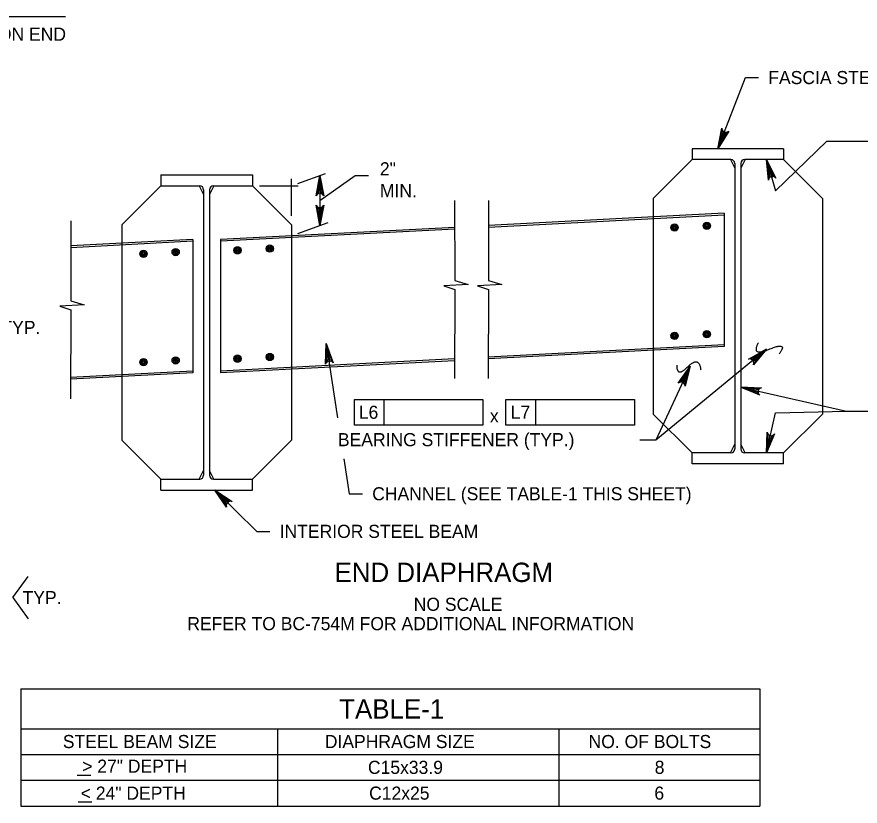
# Model space of a CAD drawing. Extents: x 638175 to 640495, y 294277 to 298435.
# Drawn here: x 639576.6 to 639769.6, y 296864 to 297044.7 of the extents above; entities that cross this region are included whole.
import ezdxf

# ---------------------------------------------------------------- set-up
doc = ezdxf.new("R2010")
doc.units = 0
for name, color, linetype in [('2', 7, 'Continuous'), ('3', 7, 'Continuous'), ('4', 7, 'Continuous'), ('5', 7, 'Continuous')]:
    doc.layers.add(name, color=color, linetype=linetype)

msp = doc.modelspace()

# ---------------------------------------------------------------- linework, layer by layer
at = {"layer": '2'}
for points in [[(639737.07, 297014.54), (639737.93, 297019.2), (639738.03, 297018.78), (639738.26, 297018.49), (639738.53, 297018.33), (639738.84, 297018.27), (639739.2, 297018.33), (639739.56, 297018.57), (639737.07, 297014.54), (639739.2, 297018.33), (639738.84, 297018.27), (639737.07, 297014.54), (639738.53, 297018.33), (639738.26, 297018.49), (639737.07, 297014.54), (639738.03, 297018.78)], [(639748.17, 297012.04), (639750.3, 297007.81), (639749.96, 297008.08), (639749.61, 297008.17), (639749.3, 297008.14), (639749.01, 297008), (639748.76, 297007.73), (639748.62, 297007.32), (639748.17, 297012.04), (639748.76, 297007.73), (639749.01, 297008), (639748.17, 297012.04), (639749.3, 297008.14), (639749.61, 297008.17), (639748.17, 297012.04), (639749.96, 297008.08)], [(639645.94, 297008.41), (639646.81, 297003.75), (639646.57, 297004.11), (639646.25, 297004.29), (639645.94, 297004.35), (639645.63, 297004.29), (639645.32, 297004.11), (639645.07, 297003.75), (639645.94, 297008.41), (639645.32, 297004.11), (639645.63, 297004.29), (639645.94, 297008.41), (639645.94, 297004.35), (639646.25, 297004.29), (639645.94, 297008.41), (639646.57, 297004.11)], [(639645.94, 296996.95), (639645.07, 297001.61), (639645.32, 297001.26), (639645.63, 297001.07), (639645.94, 297001.02), (639646.25, 297001.07), (639646.57, 297001.26), (639646.81, 297001.61), (639645.94, 296996.95), (639646.57, 297001.26), (639646.25, 297001.07), (639645.94, 296996.95), (639645.94, 297001.02), (639645.63, 297001.07), (639645.94, 296996.95), (639645.32, 297001.26)], [(639647.37, 296969.95), (639648.94, 296965.48), (639648.64, 296965.79), (639648.31, 296965.93), (639647.99, 296965.93), (639647.69, 296965.83), (639647.41, 296965.6), (639647.22, 296965.21), (639647.37, 296969.95), (639647.41, 296965.6), (639647.69, 296965.83), (639647.37, 296969.95), (639647.99, 296965.93), (639648.31, 296965.93), (639647.37, 296969.95), (639648.64, 296965.79)], [(639748.23, 296968.67), (639745.19, 296965.03), (639745.31, 296965.45), (639745.25, 296965.81), (639745.1, 296966.09), (639744.86, 296966.3), (639744.51, 296966.42), (639744.08, 296966.38), (639748.23, 296968.67), (639744.51, 296966.42), (639744.86, 296966.3), (639748.23, 296968.67), (639745.1, 296966.09), (639745.25, 296965.81), (639748.23, 296968.67), (639745.31, 296965.45)], [(639730.74, 296964.75), (639729.57, 296960.16), (639729.5, 296960.59), (639729.29, 296960.88), (639729.03, 296961.07), (639728.72, 296961.15), (639728.36, 296961.11), (639727.98, 296960.89), (639730.74, 296964.75), (639728.36, 296961.11), (639728.72, 296961.15), (639730.74, 296964.75), (639729.03, 296961.07), (639729.29, 296960.88), (639730.74, 296964.75), (639729.5, 296960.59)], [(639742.31, 296959.97), (639747.05, 296959.78), (639746.64, 296959.62), (639746.39, 296959.36), (639746.27, 296959.06), (639746.25, 296958.75), (639746.36, 296958.4), (639746.66, 296958.08), (639742.31, 296959.97), (639746.36, 296958.4), (639746.25, 296958.75), (639742.31, 296959.97), (639746.27, 296959.06), (639746.39, 296959.36), (639742.31, 296959.97), (639746.64, 296959.62)], [(639748.17, 296944.9), (639748.34, 296949.63), (639748.5, 296949.23), (639748.77, 296948.98), (639749.06, 296948.86), (639749.38, 296948.84), (639749.72, 296948.95), (639750.05, 296949.25), (639748.17, 296944.9), (639749.72, 296948.95), (639749.38, 296948.84), (639748.17, 296944.9), (639749.06, 296948.86), (639748.77, 296948.98), (639748.17, 296944.9), (639748.5, 296949.23)], [(639621.88, 296936.38), (639625.82, 296933.74), (639625.39, 296933.81), (639625.04, 296933.72), (639624.78, 296933.53), (639624.6, 296933.27), (639624.51, 296932.92), (639624.59, 296932.49), (639621.88, 296936.38), (639624.51, 296932.92), (639624.6, 296933.27), (639621.88, 296936.38), (639624.78, 296933.53), (639625.04, 296933.72), (639621.88, 296936.38), (639625.39, 296933.81)]]:
    msp.add_lwpolyline(points, dxfattribs=at)
at = {"layer": '3'}
for p, q in [((639587.69, 297044.71), (639454.93, 297044.71)), ((639737.07, 297014.54), (639743.36, 297030.82)), ((639743.36, 297030.82), (639746.36, 297030.82)), ((639750.24, 297004.88), (639761.99, 297016.29)), ((639761.99, 297016.29), (639784.7, 297016.29)), ((639748.17, 297012.04), (639750.24, 297004.88)), ((639640.87, 297006.56), (639647.25, 297008.89)), ((639645.94, 297002.68), (639654.05, 297008.43)), ((639645.94, 297008.41), (639645.94, 296996.95)), ((639654.05, 297008.43), (639657.05, 297008.43)), ((639639.4, 296999.19), (639639.4, 297007.65)), ((639632.08, 297006.03), (639641, 297006.03)), ((639676.79, 297002.71), (639676.86, 296984.36)), ((639684.51, 297002.71), (639684.57, 296984.36)), ((639588.88, 296998.05), (639588.95, 296979.7)), ((639640.87, 296995.11), (639647.85, 296997.65)), ((639679.86, 296983.48), (639674.34, 296983.17)), ((639674.34, 296983.17), (639676.85, 296982.31)), ((639676.86, 296984.36), (639679.86, 296983.48)), ((639687.58, 296983.48), (639682.06, 296983.17)), ((639682.06, 296983.17), (639684.57, 296982.31)), ((639684.57, 296984.36), (639687.58, 296983.48)), ((639676.85, 296982.31), (639676.73, 296961.96)), ((639684.57, 296982.31), (639684.45, 296961.96)), ((639588.95, 296979.7), (639591.95, 296978.82)), ((639591.95, 296978.82), (639586.43, 296978.51)), ((639586.43, 296978.51), (639588.94, 296977.65)), ((639588.94, 296977.65), (639588.82, 296957.3)), ((639647.37, 296969.95), (639649.99, 296952.93)), ((639748.23, 296968.67), (639722.87, 296947.78)), ((639730.74, 296964.75), (639722.87, 296947.78)), ((639742.31, 296959.97), (639766.48, 296954.44)), ((639653.85, 296957.12), (639683.24, 296957.12)), ((639653.85, 296951.22), (639653.85, 296957.12)), ((639660.69, 296951.22), (639660.69, 296957.12)), ((639683.24, 296957.12), (639683.24, 296951.22)), ((639688.54, 296957.12), (639717.94, 296957.12)), ((639688.54, 296951.22), (639688.54, 296957.12)), ((639695.39, 296951.22), (639695.39, 296957.12)), ((639717.94, 296957.12), (639717.94, 296951.22)), ((639748.17, 296944.9), (639750.24, 296954.09)), ((639750.24, 296954.09), (639766.48, 296954.44)), ((639766.48, 296954.44), (639789.53, 296954.44)), ((639683.24, 296951.22), (639653.85, 296951.22)), ((639717.94, 296951.22), (639688.54, 296951.22)), ((639722.87, 296947.78), (639719.2, 296947.78)), ((639651.44, 296943.53), (639652.67, 296935.54)), ((639621.88, 296936.38), (639631.48, 296926.94)), ((639652.67, 296935.54), (639655.67, 296935.54)), ((639631.48, 296926.94), (639634.48, 296926.94)), ((639575.61, 296911.77), (639579.18, 296916.61)), ((639575.61, 296911.77), (639579.18, 296906.93)), ((639577.5, 296890.9), (639746.63, 296890.9)), ((639577.5, 296890.9), (639577.5, 296864.03)), ((639746.63, 296890.9), (639746.63, 296864.03)), ((639577.5, 296881.75), (639746.63, 296881.75)), ((639636.23, 296881.75), (639636.23, 296864.03)), ((639700.65, 296881.75), (639700.65, 296864.03)), ((639577.5, 296875.84), (639746.63, 296875.84)), ((639593.48, 296871.05), (639590.39, 296871.05)), ((639577.5, 296869.94), (639746.63, 296869.94)), ((639577.5, 296864.03), (639746.63, 296864.03)), ((639593.71, 296864.92), (639590.62, 296864.92))]:
    msp.add_line(p, q, dxfattribs=at)
for points in [[(639738.61, 297017.16), (639737.68, 297017.52), (639737.07, 297014.54)], [(639748.52, 297009.02), (639749.48, 297009.3), (639748.17, 297012.04)], [(639645.44, 297005.41), (639646.44, 297005.41), (639645.94, 297008.41)], [(639645.44, 296999.95), (639646.44, 296999.95), (639645.94, 296996.95)], [(639647.33, 296966.91), (639648.32, 296967.06), (639647.37, 296969.95)], [(639745.12, 296958.81), (639745.35, 296959.79), (639742.31, 296959.97)], [(639749.31, 296947.71), (639748.34, 296947.93), (639748.17, 296944.9)], [(639623.67, 296933.92), (639624.37, 296934.63), (639621.89, 296936.38)]]:
    msp.add_lwpolyline(points, close=True, dxfattribs=at)
for points in [[(639746.33, 296970.12), (639744.5, 296966.83), (639753.29, 296970.49), (639751.1, 296967.56)], [(639727.63, 296965), (639727.63, 296962.06), (639732.77, 296967.19), (639733.13, 296963.9)]]:
    msp.add_open_spline(points, degree=2, dxfattribs=at)
at = {"layer": '4'}
for p, q in [((639752.1, 297014.54), (639731.14, 297014.54)), ((639731.14, 297012.04), (639722.23, 297003.13)), ((639740.04, 297012.04), (639731.14, 297012.04)), ((639739.95, 297012.04), (639740.93, 297010.07)), ((639743.29, 297012.04), (639742.31, 297010.07)), ((639752.1, 297012.04), (639743.2, 297012.04)), ((639752.1, 297012.04), (639761.01, 297003.13)), ((639740.93, 297011.15), (639740.93, 296945.78)), ((639742.31, 297011.15), (639742.31, 296945.78)), ((639609.52, 297008.53), (639630.49, 297008.53)), ((639609.52, 297006.03), (639600.62, 296997.12)), ((639609.52, 297006.03), (639618.43, 297006.03)), ((639618.33, 297006.03), (639619.32, 297004.06)), ((639619.32, 297005.14), (639619.32, 296939.77)), ((639621.68, 297006.03), (639620.7, 297004.06)), ((639620.7, 297005.14), (639620.7, 296939.77)), ((639621.59, 297006.03), (639630.49, 297006.03)), ((639630.49, 297006.03), (639639.4, 296997.12)), ((639722.23, 297003.13), (639722.23, 296998.89)), ((639761.01, 297003.13), (639761.01, 296953.8)), ((639722.23, 296998.89), (639722.23, 296968.38)), ((639738.47, 296999.74), (639738.47, 296969.23)), ((639600.62, 296997.12), (639600.62, 296992.88)), ((639639.4, 296997.12), (639639.4, 296994.57)), ((639639.4, 296994.57), (639639.4, 296964.06)), ((639600.62, 296992.88), (639600.62, 296962.37)), ((639616.86, 296993.72), (639616.86, 296963.21)), ((639623.16, 296993.72), (639623.16, 296963.21)), ((639722.23, 296968.38), (639722.23, 296953.8)), ((639639.4, 296964.06), (639639.4, 296947.79)), ((639600.62, 296962.37), (639600.62, 296947.79)), ((639722.23, 296953.8), (639731.14, 296944.9)), ((639752.1, 296944.9), (639761.01, 296953.8)), ((639600.62, 296947.79), (639609.52, 296938.88)), ((639630.49, 296938.88), (639639.4, 296947.79)), ((639739.95, 296944.9), (639740.93, 296946.86)), ((639743.29, 296944.9), (639742.31, 296946.86)), ((639740.04, 296944.9), (639731.14, 296944.9)), ((639752.1, 296944.9), (639743.2, 296944.9)), ((639752.1, 296942.4), (639731.14, 296942.4)), ((639618.33, 296938.88), (639619.32, 296940.85)), ((639621.68, 296938.88), (639620.7, 296940.85)), ((639609.52, 296938.88), (639618.43, 296938.88)), ((639621.59, 296938.88), (639630.49, 296938.88)), ((639609.52, 296936.38), (639630.49, 296936.38))]:
    msp.add_line(p, q, dxfattribs=at)
for centre, radius in [((639727.15, 296996.48), 0.833), ((639727.15, 296996.48), 0.625), ((639727.15, 296996.48), 0.417), ((639727.15, 296996.48), 0.208), ((639734.53, 296996.88), 0.833), ((639734.53, 296996.88), 0.625), ((639734.53, 296996.88), 0.417), ((639734.53, 296996.88), 0.208), ((639727.15, 296971.68), 0.833), ((639727.15, 296971.68), 0.625), ((639727.15, 296971.68), 0.417), ((639727.15, 296971.68), 0.208), ((639734.53, 296972.08), 0.833), ((639734.53, 296972.08), 0.625), ((639734.53, 296972.08), 0.417), ((639734.53, 296972.08), 0.208)]:
    msp.add_circle(centre, radius, dxfattribs=at)
for centre, start, end in [((639740.04, 297011.15), 0, 90), ((639743.2, 297011.15), 90, 180), ((639618.43, 297005.14), 0, 90), ((639621.58, 297005.14), 90, 180), ((639740.04, 296945.79), 270, 0), ((639743.2, 296945.79), 180, 270), ((639618.43, 296939.77), 270, 0), ((639621.58, 296939.77), 180, 270)]:
    msp.add_arc(centre, 0.889, start, end, dxfattribs=at)
at = {"layer": '5'}
for p, q in [((639731.14, 297014.54), (639731.14, 297012.04)), ((639752.1, 297014.54), (639752.1, 297012.04)), ((639609.52, 297008.53), (639609.52, 297006.03)), ((639630.49, 297008.53), (639630.49, 297006.03)), ((639738.47, 296999.74), (639684.53, 296996.92)), ((639738.47, 296999.35), (639684.53, 296996.53)), ((639676.82, 296996.52), (639623.16, 296993.72)), ((639676.82, 296996.13), (639623.16, 296993.33)), ((639616.86, 296993.72), (639588.9, 296992.27)), ((639616.86, 296993.33), (639588.91, 296991.87)), ((639738.47, 296969.62), (639684.48, 296966.81)), ((639738.47, 296969.23), (639684.47, 296966.41)), ((639676.76, 296966.4), (639623.16, 296963.61)), ((639676.76, 296966.01), (639623.16, 296963.21)), ((639616.86, 296963.61), (639588.85, 296962.15)), ((639616.86, 296963.21), (639588.85, 296961.75)), ((639731.14, 296942.4), (639731.14, 296944.9)), ((639752.1, 296942.4), (639752.1, 296944.9)), ((639609.52, 296936.38), (639609.52, 296938.88)), ((639630.49, 296936.38), (639630.49, 296938.88))]:
    msp.add_line(p, q, dxfattribs=at)
for centre, radius in [((639605.54, 296990.47), 0.833), ((639605.54, 296990.47), 0.625), ((639605.54, 296990.47), 0.417), ((639605.54, 296990.47), 0.208), ((639612.92, 296990.87), 0.833), ((639612.92, 296990.87), 0.625), ((639612.92, 296990.87), 0.417), ((639612.92, 296990.87), 0.208), ((639627.09, 296991.27), 0.833), ((639627.09, 296991.27), 0.625), ((639627.09, 296991.27), 0.417), ((639627.09, 296991.27), 0.208), ((639634.47, 296991.66), 0.833), ((639634.47, 296991.66), 0.625), ((639634.47, 296991.66), 0.417), ((639634.47, 296991.66), 0.208), ((639634.47, 296966.85), 0.833), ((639634.47, 296966.85), 0.625), ((639605.54, 296965.67), 0.833), ((639605.54, 296965.67), 0.625), ((639605.54, 296965.67), 0.417), ((639605.54, 296965.67), 0.208), ((639612.92, 296966.07), 0.833), ((639612.92, 296966.07), 0.625), ((639612.92, 296966.07), 0.417), ((639612.92, 296966.07), 0.208), ((639627.09, 296966.47), 0.833), ((639627.09, 296966.47), 0.625), ((639627.09, 296966.47), 0.417), ((639627.09, 296966.47), 0.208), ((639634.47, 296966.85), 0.417), ((639634.47, 296966.85), 0.208)]:
    msp.add_circle(centre, radius, dxfattribs=at)

# ---------------------------------------------------------------- texts
at = {"layer": '3'}
for s, height, p in [('EXPANSION END', 3, (639554.82, 297039.25)), ('FASCIA STEEL BEAM', 3, (639748.6, 297029.32)), ('2"', 3, (639659.68, 297008.43)), ('MIN. ', 3, (639659.68, 297003.43)), ('TYP.', 3, (639573.02, 296972.12)), ('L6', 3, (639654.85, 296952.7)), ('x', 3, (639684.86, 296951.87)), ('L7', 3, (639689.63, 296952.7)), ('BEARING STIFFENER (TYP.)', 3, (639650.06, 296946.43)), ('CHANNEL (SEE TABLE-1 THIS SHEET)', 3, (639657.92, 296934.04)), ('INTERIOR STEEL BEAM', 3, (639636.73, 296925.44)), ('END DIAPHRAGM', 4.4292, (639649.3, 296915.34)), ('TYP.', 3, (639577.86, 296910.27)), ('NO SCALE', 3, (639667.42, 296908.74)), ('REFER TO BC-754M FOR ADDITIONAL INFORMATION', 3, (639615.58, 296904.31)), ('TABLE-1', 4.429, (639650.37, 296884.07)), ('STEEL BEAM SIZE', 3, (639587.08, 296877.32)), ('DIAPHRAGM SIZE', 3, (639647.07, 296877.32)), ('NO. OF BOLTS', 3, (639707.46, 296877.32)), ('> 27" DEPTH', 3, (639591.51, 296871.68)), ('C15x33.9', 3, (639656.94, 296871.41)), ('8', 3, (639722.6, 296871.42)), ('< 24" DEPTH', 3, (639591.18, 296865.51)), ('C12x25', 3, (639657.21, 296865.51)), ('6', 3, (639722.52, 296865.51))]:
    msp.add_text(s, height=height, dxfattribs=at).set_placement(p)

doc.saveas('drawing.dxf')
